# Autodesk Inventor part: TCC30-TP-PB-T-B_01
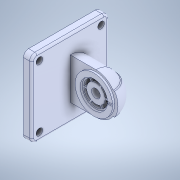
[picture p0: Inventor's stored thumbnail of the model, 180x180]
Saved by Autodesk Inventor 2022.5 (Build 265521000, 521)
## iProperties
Created: 2023-09
Part Number: TCC30-TP-PB-T-B_01
Material: 一般
Document SubType Name: Modeling
Designer: ImaoCorp
Density: 1 g/cm^3
Appearance: 既定
Author: ImaoCorp
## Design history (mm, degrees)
feature "TCC30-TP-PB-T-B_01"
node "ソリッド1"
